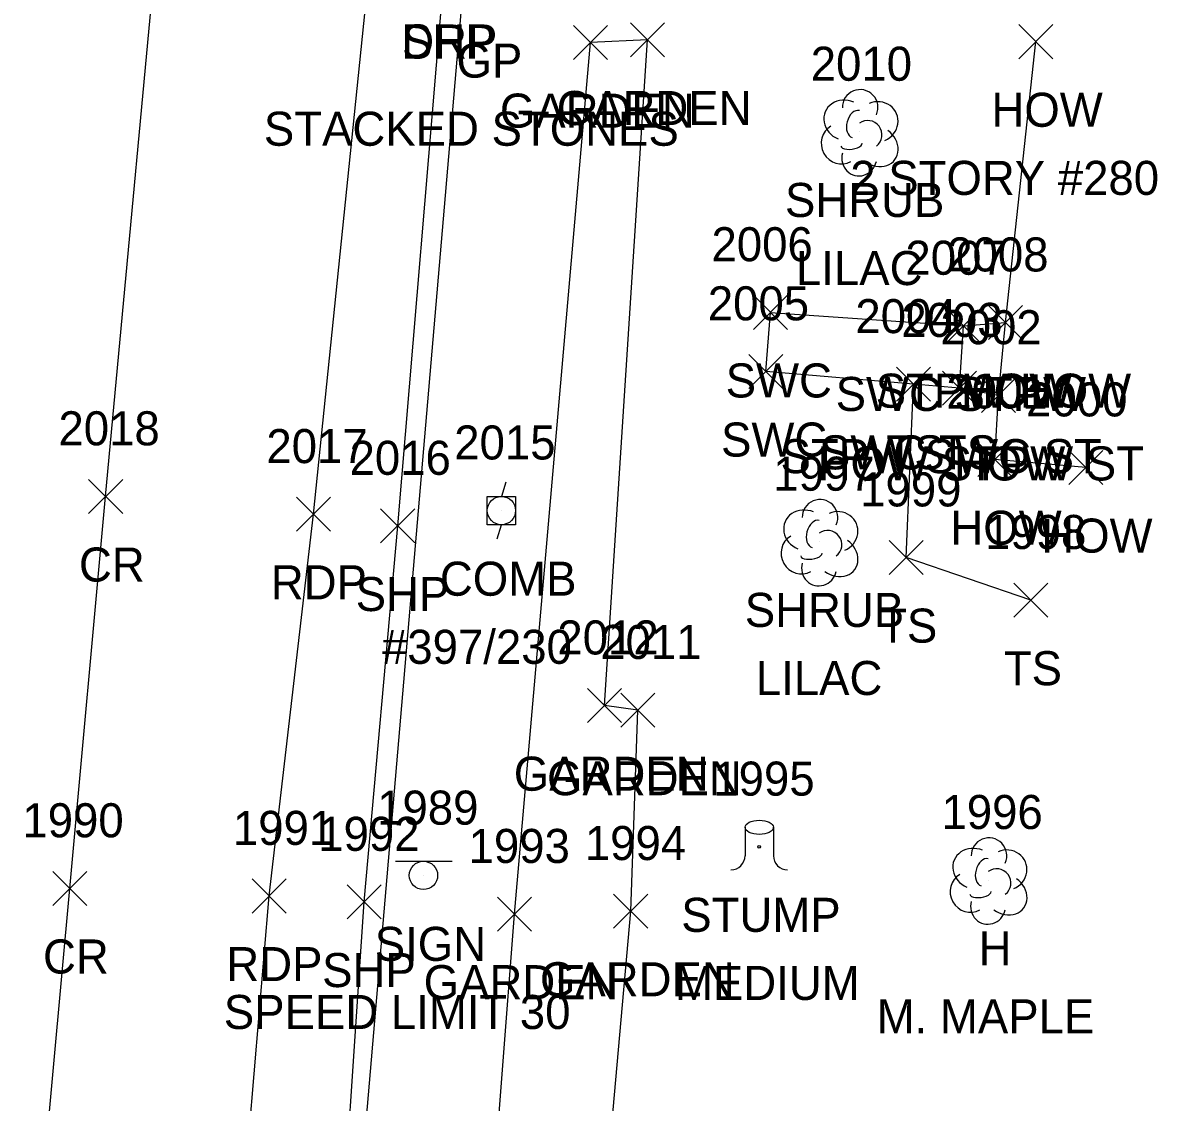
# Model space of a CAD drawing. Extents: x 1653908 to 1654393, y 539913 to 544256.
# Drawn here: x 1654091.7 to 1654158.4, y 541903.2 to 541966.6 of the extents above; entities that cross this region are included whole.
import ezdxf

# ---------------------------------------------------------------- set-up
doc = ezdxf.new("R2010")
doc.units = 0
for name, color, linetype in [('DCP', 7, 'Continuous'), ('L_A', 7, 'Continuous'), ('L_C', 7, 'Continuous'), ('L_I', 7, 'Continuous'), ('L_TIC', 7, 'Continuous'), ('LAPB', 7, 'Continuous'), ('LBC', 7, 'Continuous'), ('LBF', 7, 'Continuous'), ('LELB', 7, 'Continuous'), ('LSH', 7, 'Continuous'), ('LTD', 7, 'Continuous'), ('LTS', 7, 'Continuous'), ('P_A', 7, 'Continuous'), ('P_I', 7, 'Continuous'), ('P_TIC', 7, 'Continuous'), ('PET', 7, 'Continuous'), ('PRC', 7, 'Continuous'), ('PSP', 7, 'Continuous'), ('R_A', 7, 'Continuous'), ('R_C', 7, 'Continuous'), ('R_I', 7, 'Continuous'), ('R_TIC', 7, 'Continuous'), ('RSW', 7, 'Continuous'), ('S_A', 7, 'Continuous'), ('S_C', 7, 'Continuous'), ('S_I', 7, 'Continuous'), ('SSGN', 7, 'Continuous'), ('U_A', 7, 'Continuous'), ('U_C', 7, 'Continuous'), ('U_I', 7, 'Continuous'), ('UP', 7, 'Continuous')]:
    doc.layers.add(name, color=color, linetype=linetype)

msp = doc.modelspace()

# ---------------------------------------------------------------- linework, layer by layer
at = {"layer": 'DCP'}
msp.add_lwpolyline([(1654106.161, 541835.083), (1654119.744, 541993.79)], dxfattribs=at)
at = {"layer": 'L_TIC'}
for points in [[(1654124.073, 541964.48), (1654126.073, 541966.48)], [(1654126.073, 541964.48), (1654124.073, 541966.48)], [(1654124.073, 541964.48), (1654126.073, 541966.48)], [(1654126.073, 541964.48), (1654124.073, 541966.48)], [(1654127.413, 541964.634), (1654129.413, 541966.634)], [(1654129.413, 541964.634), (1654127.413, 541966.634)], [(1654150.228, 541964.532), (1654152.228, 541966.532)], [(1654152.228, 541964.532), (1654150.228, 541966.532)], [(1654145.976, 541947.842), (1654147.976, 541949.842)], [(1654147.976, 541947.842), (1654145.976, 541949.842)], [(1654148.434, 541948.035), (1654150.434, 541950.035)], [(1654150.434, 541948.035), (1654148.434, 541950.035)], [(1654148.434, 541948.035), (1654150.434, 541950.035)], [(1654150.434, 541948.035), (1654148.434, 541950.035)], [(1654143.039, 541944.412), (1654145.039, 541946.412)], [(1654145.039, 541944.412), (1654143.039, 541946.412)], [(1654145.737, 541944.19), (1654147.737, 541946.19)], [(1654147.737, 541944.19), (1654145.737, 541946.19)], [(1654148.029, 541943.761), (1654150.029, 541945.761)], [(1654150.029, 541943.761), (1654148.029, 541945.761)], [(1654148.029, 541943.761), (1654150.029, 541945.761)], [(1654150.029, 541943.761), (1654148.029, 541945.761)], [(1654147.815, 541939.986), (1654149.815, 541941.986)], [(1654149.815, 541939.986), (1654147.815, 541941.986)], [(1654153.154, 541939.523), (1654155.154, 541941.523)], [(1654155.154, 541939.523), (1654153.154, 541941.523)], [(1654142.605, 541934.237), (1654144.605, 541936.237)], [(1654144.605, 541934.237), (1654142.605, 541936.237)], [(1654149.93, 541931.736), (1654151.93, 541933.736)], [(1654151.93, 541931.736), (1654149.93, 541933.736)], [(1654124.891, 541925.542), (1654126.891, 541927.542)], [(1654126.891, 541925.542), (1654124.891, 541927.542)], [(1654126.843, 541925.277), (1654128.843, 541927.277)], [(1654128.843, 541925.277), (1654126.843, 541927.277)], [(1654119.598, 541913.299), (1654121.598, 541915.299)], [(1654121.598, 541913.299), (1654119.598, 541915.299)], [(1654126.425, 541913.47), (1654128.425, 541915.47)], [(1654128.425, 541913.47), (1654126.425, 541915.47)]]:
    msp.add_lwpolyline(points, dxfattribs=at)
at = {"layer": 'LAPB'}
for points in [[(1654147.333, 541895.826), (1654125.903, 541897.3), (1654127.425, 541914.47), (1654127.843, 541926.277), (1654125.891, 541926.542), (1654128.413, 541965.634), (1654125.073, 541965.48)], [(1654147.333, 541895.826), (1654146.94, 541894.469), (1654125.528, 541894.416), (1654119.161, 541895.504), (1654120.598, 541914.299), (1654125.073, 541965.48)]]:
    msp.add_lwpolyline(points, dxfattribs=at)
at = {"layer": 'LBC'}
msp.add_lwpolyline([(1654154.154, 541940.523), (1654148.815, 541940.986), (1654149.029, 541944.761), (1654149.434, 541949.035), (1654151.228, 541965.532)], dxfattribs=at)
at = {"layer": 'LBF'}
msp.add_lwpolyline([(1654149.029, 541944.761), (1654146.737, 541945.19), (1654146.976, 541948.842), (1654149.434, 541949.035)], dxfattribs=at)
at = {"layer": 'LELB'}
msp.add_lwpolyline([(1654150.93, 541932.736), (1654143.605, 541935.237), (1654144.039, 541945.412)], dxfattribs=at)
at = {"layer": 'LSH'}
for p, q in [((1654140.857, 541960.235), (1654140.857, 541960.235)), ((1654140.857, 541960.235), (1654140.857, 541960.235)), ((1654138.497, 541936.161), (1654138.497, 541936.161)), ((1654138.497, 541936.161), (1654138.497, 541936.161))]:
    msp.add_line(p, q, dxfattribs=at)
for centre in [(1654140.903, 541961.669), (1654138.544, 541937.595)]:
    msp.add_arc(centre, 1.047, 335.52715, 180.95627, dxfattribs=at)
for centre, major_axis, ratio, start_param, end_param in [((1654140.065, 541960.902), (1.21, -0.512), 0.895232, 1.570796, 4.712389), ((1654141.898, 541960.819), (-1.141, -0.483), 0.949671, 1.570796, 4.712389), ((1654140.648, 541960.694), (-0.208, -0.792), 0.645439, 3.141593, 6.283185), ((1654141.357, 541960.069), (-0.5, 0.667), 0.989748, 3.141593, 6.283185), ((1654139.773, 541959.527), (0.584, -1.042), 0.959034, 3.141593, 6.283185), ((1654141.857, 541959.402), (-1.09, 0.792), 0.841452, 1.570796, 4.712389), ((1654140.398, 541959.485), (-0.625, -0.083), 0.423636, 0, 3.141593), ((1654140.857, 541958.735), (0.265, 1.061), 0.942809, 1.570796, 4.712389), ((1654137.705, 541936.828), (1.21, -0.512), 0.895232, 1.570796, 4.712389), ((1654139.539, 541936.745), (-1.141, -0.483), 0.949671, 1.570796, 4.712389), ((1654138.289, 541936.62), (-0.208, -0.792), 0.645439, 3.141593, 6.283185), ((1654138.997, 541935.995), (-0.5, 0.667), 0.989748, 3.141593, 6.283185), ((1654137.414, 541935.453), (0.584, -1.042), 0.959034, 3.141593, 6.283185), ((1654139.497, 541935.328), (-1.09, 0.792), 0.841452, 1.570796, 4.712389), ((1654138.497, 541934.661), (0.265, 1.061), 0.942809, 1.570796, 4.712389), ((1654138.039, 541935.411), (-0.625, -0.083), 0.423636, 0, 3.141593)]:
    msp.add_ellipse(centre, major_axis=major_axis, ratio=ratio, start_param=start_param, end_param=end_param, dxfattribs=at)
at = {"layer": 'LTD'}
msp.add_line((1654148.426, 541916.292), (1654148.426, 541916.292), dxfattribs=at)
msp.add_line((1654148.426, 541916.292), (1654148.426, 541916.292), dxfattribs=at)
msp.add_arc((1654148.473, 541917.726), 1.047, 335.52715, 180.95627, dxfattribs=at)
for centre, major_axis, ratio, start_param, end_param in [((1654147.634, 541916.958), (1.21, -0.512), 0.895232, 1.570796, 4.712389), ((1654149.468, 541916.875), (-1.141, -0.483), 0.949671, 1.570796, 4.712389), ((1654148.218, 541916.75), (-0.208, -0.792), 0.645439, 3.141593, 6.283185), ((1654148.926, 541916.125), (-0.5, 0.667), 0.989748, 3.141593, 6.283185), ((1654147.343, 541915.583), (0.584, -1.042), 0.959034, 3.141593, 6.283185), ((1654149.426, 541915.459), (-1.09, 0.792), 0.841452, 1.570796, 4.712389), ((1654147.968, 541915.542), (-0.625, -0.083), 0.423636, 0, 3.141593), ((1654148.426, 541914.792), (0.265, 1.061), 0.942809, 1.570796, 4.712389)]:
    msp.add_ellipse(centre, major_axis=major_axis, ratio=ratio, start_param=start_param, end_param=end_param, dxfattribs=at)
at = {"layer": 'LTS'}
for p, q in [((1654134.143, 541919.392), (1654134.143, 541917.726)), ((1654135.809, 541919.226), (1654135.809, 541919.392)), ((1654135.809, 541919.392), (1654135.809, 541917.726)), ((1654134.976, 541918.25), (1654134.976, 541918.25)), ((1654134.976, 541918.25), (1654134.976, 541918.25)), ((1654134.976, 541918.226), (1654134.976, 541918.226))]:
    msp.add_line(p, q, dxfattribs=at)
msp.add_circle((1654134.976, 541918.25), 0.0833, dxfattribs=at)
for centre, start, end in [((1654133.309, 541917.726), 270, 360), ((1654136.643, 541917.726), 180, 270)]:
    msp.add_arc(centre, 0.833, start, end, dxfattribs=at)
msp.add_ellipse((1654134.976, 541919.392), major_axis=(-0.833, 0), ratio=0.5, dxfattribs=at)
at = {"layer": 'P_TIC'}
for points in [[(1654095.589, 541937.824), (1654097.589, 541939.824)], [(1654097.589, 541937.824), (1654095.589, 541939.824)], [(1654107.801, 541936.78), (1654109.801, 541938.78)], [(1654109.801, 541936.78), (1654107.801, 541938.78)], [(1654112.741, 541936.092), (1654114.741, 541938.092)], [(1654114.741, 541936.092), (1654112.741, 541938.092)], [(1654093.478, 541914.806), (1654095.478, 541916.806)], [(1654095.478, 541914.806), (1654093.478, 541916.806)], [(1654105.19, 541914.359), (1654107.19, 541916.359)], [(1654107.19, 541914.359), (1654105.19, 541916.359)], [(1654110.767, 541914.009), (1654112.767, 541916.009)], [(1654112.767, 541914.009), (1654110.767, 541916.009)]]:
    msp.add_lwpolyline(points, dxfattribs=at)
at = {"layer": 'PET'}
msp.add_lwpolyline([(1654079.776, 541659.551), (1654080.091, 541663.585), (1654084.434, 541705.035), (1654088.467, 541726.588), (1654090.823, 541750.421), (1654095.245, 541793.922), (1654098.735, 541834.906), (1654102.668, 541873.549), (1654106.19, 541915.359), (1654108.801, 541937.78), (1654112.78, 541976.541), (1654113.712, 541994.764), (1654118.507, 542040.261), (1654122.37, 542081.456), (1654125.512, 542120.567), (1654128.858, 542154.493), (1654132.07, 542197.521), (1654136.387, 542232.744)], dxfattribs=at)
at = {"layer": 'PRC'}
msp.add_lwpolyline([(1654071.378, 541669.623), (1654074.689, 541707.082), (1654077.078, 541730.589), (1654080.001, 541762.219), (1654083.127, 541795.122), (1654087.252, 541836.363), (1654090.634, 541873.535), (1654094.478, 541915.806), (1654096.589, 541938.824), (1654100.212, 541977.673), (1654102.082, 541996.315), (1654106.328, 542040.19), (1654109.98, 542082.612), (1654113.749, 542122.62), (1654117.046, 542159.879), (1654120.869, 542199.278), (1654124.055, 542234.043)], dxfattribs=at)
at = {"layer": 'PSP'}
msp.add_lwpolyline([(1654094.458, 541721.214), (1654096.104, 541749.586), (1654101.261, 541800.15), (1654104.956, 541834.324), (1654108.508, 541872.884), (1654110.153, 541890.734), (1654111.767, 541915.009), (1654113.741, 541937.092), (1654116.462, 541969.541), (1654117.65, 541994.217), (1654121.735, 542040.282), (1654126.757, 542081.182), (1654129.731, 542120.034), (1654133.658, 542152.736), (1654138.064, 542196.396), (1654141.276, 542231.97)], dxfattribs=at)
at = {"layer": 'R_TIC'}
for points in [[(1654134.643, 541948.635), (1654136.643, 541950.635)], [(1654136.643, 541948.635), (1654134.643, 541950.635)], [(1654145.976, 541947.842), (1654147.976, 541949.842)], [(1654147.976, 541947.842), (1654145.976, 541949.842)], [(1654134.371, 541945.164), (1654136.371, 541947.164)], [(1654136.371, 541945.164), (1654134.371, 541947.164)], [(1654143.039, 541944.412), (1654145.039, 541946.412)], [(1654145.039, 541944.412), (1654143.039, 541946.412)], [(1654145.737, 541944.19), (1654147.737, 541946.19)], [(1654147.737, 541944.19), (1654145.737, 541946.19)]]:
    msp.add_lwpolyline(points, dxfattribs=at)
at = {"layer": 'RSW'}
msp.add_lwpolyline([(1654146.737, 541945.19), (1654144.039, 541945.412), (1654135.371, 541946.164), (1654135.643, 541949.635), (1654146.976, 541948.842)], dxfattribs=at)
at = {"layer": 'SSGN'}
for p, q in [((1654113.608, 541917.401), (1654116.942, 541917.401)), ((1654115.255, 541916.568), (1654115.255, 541916.568))]:
    msp.add_line(p, q, dxfattribs=at)
msp.add_circle((1654115.255, 541916.568), 0.833, dxfattribs=at)
at = {"layer": 'UP'}
for p, q in [((1654120.084, 541939.66), (1654119.834, 541938.827)), ((1654119, 541937.16), (1654119, 541938.827)), ((1654119, 541938.827), (1654120.667, 541938.827)), ((1654120.667, 541938.827), (1654120.667, 541937.16)), ((1654119.834, 541937.993), (1654119.834, 541937.993)), ((1654120.667, 541937.16), (1654119, 541937.16)), ((1654119.584, 541936.327), (1654119.834, 541937.16))]:
    msp.add_line(p, q, dxfattribs=at)
msp.add_circle((1654119.834, 541937.993), 0.833, dxfattribs=at)

# ---------------------------------------------------------------- texts
at = {"layer": 'L_A'}
for s, p in [('GARDEN', (1654119.742, 541960.48)), ('GARDEN', (1654119.742, 541960.48)), ('GARDEN', (1654123.083, 541960.634)), ('HOW', (1654148.614, 541960.532)), ('SHRUB', (1654136.487, 541955.235)), ('SWC STPW', (1654139.464, 541943.842)), ('STPW HOW', (1654141.813, 541944.035)), ('HOW', (1654146.82, 541944.035)), ('STPW SWC ST', (1654136.225, 541940.19)), ('TS', (1654142.448, 541940.412)), ('HOW STPW ST', (1654138.407, 541939.761)), ('HOW', (1654146.415, 541939.761)), ('HOW', (1654146.201, 541935.986)), ('HOW', (1654151.54, 541935.523)), ('SHRUB', (1654134.127, 541931.161)), ('TS', (1654142.014, 541930.237)), ('TS', (1654149.34, 541927.736)), ('GARDEN', (1654120.56, 541921.542)), ('GARDEN', (1654122.512, 541921.277)), ('STUMP', (1654130.397, 541913.253)), ('H', (1654147.859, 541911.292)), ('GARDEN', (1654115.267, 541909.299)), ('GARDEN', (1654122.094, 541909.47))]:
    msp.add_text(s, height=2, dxfattribs=at).set_placement(p)
at = {"layer": 'L_C'}
for s, p in [('2 STORY #280', (1654140.323, 541956.532)), ('LILAC', (1654137.132, 541951.235)), ('LILAC', (1654134.773, 541927.161)), ('MEDIUM', (1654130.027, 541909.253)), ('M. MAPLE', (1654141.875, 541907.292))]:
    msp.add_text(s, height=2, dxfattribs=at).set_placement(p)
at = {"layer": 'L_I'}
for s, p in [('2010', (1654137.999, 541963.235)), ('2007', (1654143.559, 541951.842)), ('2008', (1654146.017, 541952.035)), ('2008', (1654146.017, 541952.035)), ('2004', (1654140.621, 541948.412)), ('2003', (1654143.32, 541948.19)), ('2002', (1654145.612, 541947.761)), ('2002', (1654145.612, 541947.761)), ('2001', (1654145.965, 541943.986)), ('2000', (1654150.65, 541943.523)), ('1997', (1654135.804, 541939.161)), ('1999', (1654140.904, 541938.237)), ('1998', (1654148.238, 541935.736)), ('2012', (1654123.12, 541929.542)), ('2011', (1654125.638, 541929.277)), ('1995', (1654132.279, 541921.253)), ('1996', (1654145.678, 541919.292)), ('1993', (1654117.905, 541917.299)), ('1994', (1654124.732, 541917.47))]:
    msp.add_text(s, height=2, dxfattribs=at).set_placement(p)
at = {"layer": 'P_A'}
for s, p in [('SHP', (1654113.997, 541964.541)), ('CR', (1654095.022, 541933.824)), ('RDP', (1654106.289, 541932.78)), ('SHP', (1654111.276, 541932.092)), ('CR', (1654092.911, 541910.806)), ('RDP', (1654103.678, 541910.359)), ('SHP', (1654109.303, 541910.009))]:
    msp.add_text(s, height=2, dxfattribs=at).set_placement(p)
at = {"layer": 'P_I'}
for s, p in [('2018', (1654093.817, 541941.824)), ('2017', (1654106.029, 541940.78)), ('2016', (1654110.914, 541940.092)), ('1990', (1654091.699, 541918.806)), ('1991', (1654104.064, 541918.359)), ('1992', (1654109.075, 541918.009))]:
    msp.add_text(s, height=2, dxfattribs=at).set_placement(p)
at = {"layer": 'R_A'}
for s, p in [('DRP', (1654113.95, 541964.541)), ('GP', (1654117.195, 541963.418)), ('SWC', (1654133.005, 541944.635)), ('SWC STPW', (1654139.464, 541943.842)), ('SWC', (1654132.733, 541941.164)), ('STPW SWC ST', (1654136.225, 541940.19)), ('SWC TS', (1654138.543, 541940.412))]:
    msp.add_text(s, height=2, dxfattribs=at).set_placement(p)
at = {"layer": 'R_C'}
msp.add_text('STACKED STONES', height=2, dxfattribs=at).set_placement((1654105.881, 541959.418))
at = {"layer": 'R_I'}
for s, p in [('2006', (1654132.171, 541952.635)), ('2007', (1654143.559, 541951.842)), ('2005', (1654131.954, 541949.164)), ('2004', (1654140.621, 541948.412)), ('2003', (1654143.32, 541948.19))]:
    msp.add_text(s, height=2, dxfattribs=at).set_placement(p)
at = {"layer": 'S_A'}
msp.add_text('SIGN', height=2, dxfattribs=at).set_placement((1654112.393, 541911.548))
at = {"layer": 'S_C'}
msp.add_text('SPEED LIMIT 30', height=2, dxfattribs=at).set_placement((1654103.528, 541907.548))
at = {"layer": 'S_I'}
msp.add_text('1989', height=2, dxfattribs=at).set_placement((1654112.535, 541919.548))
at = {"layer": 'U_A'}
msp.add_text('COMB', height=2, dxfattribs=at).set_placement((1654116.22, 541932.993))
at = {"layer": 'U_C'}
msp.add_text('#397/230', height=2, dxfattribs=at).set_placement((1654112.818, 541928.993))
at = {"layer": 'U_I'}
msp.add_text('2015', height=2, dxfattribs=at).set_placement((1654117.062, 541940.993))

doc.saveas('drawing.dxf')
